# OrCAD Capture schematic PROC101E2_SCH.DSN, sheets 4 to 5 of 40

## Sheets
4 09.SOC POWER: size C; title: SOC POWER
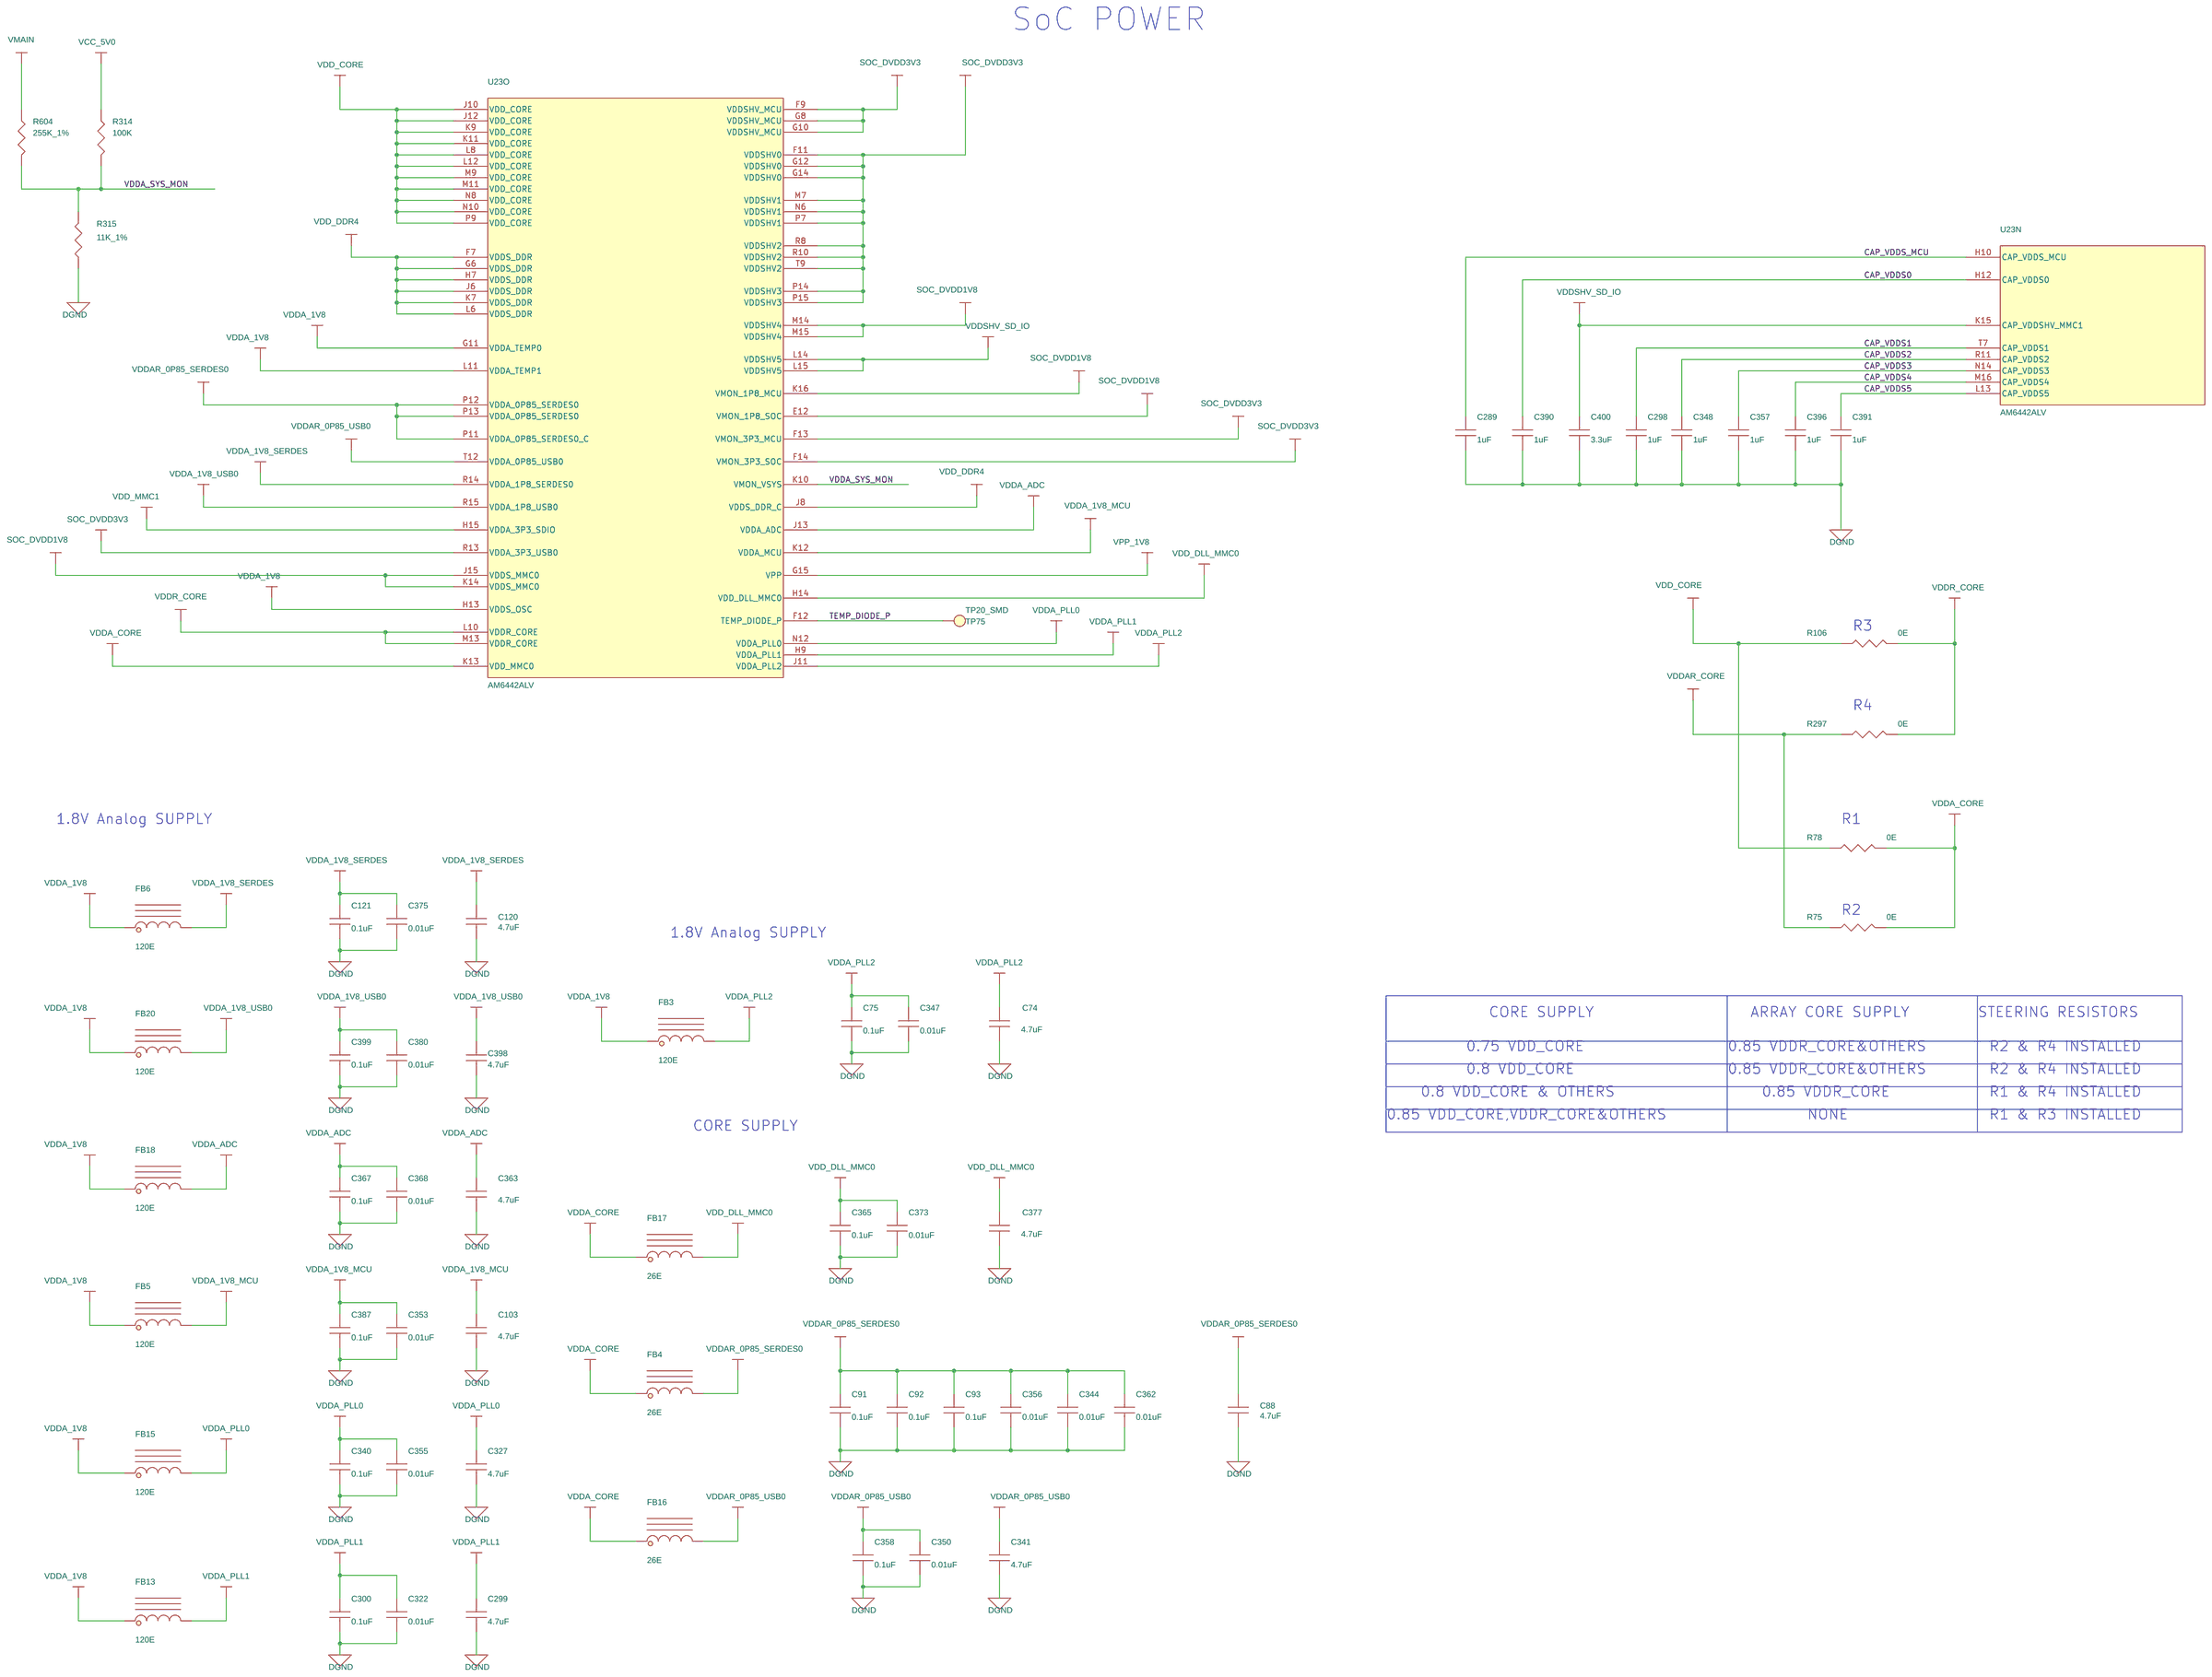
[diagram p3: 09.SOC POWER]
5 30.PCIe INTERFACE: size C; title: PCIe INTERFACE; note: PROC067
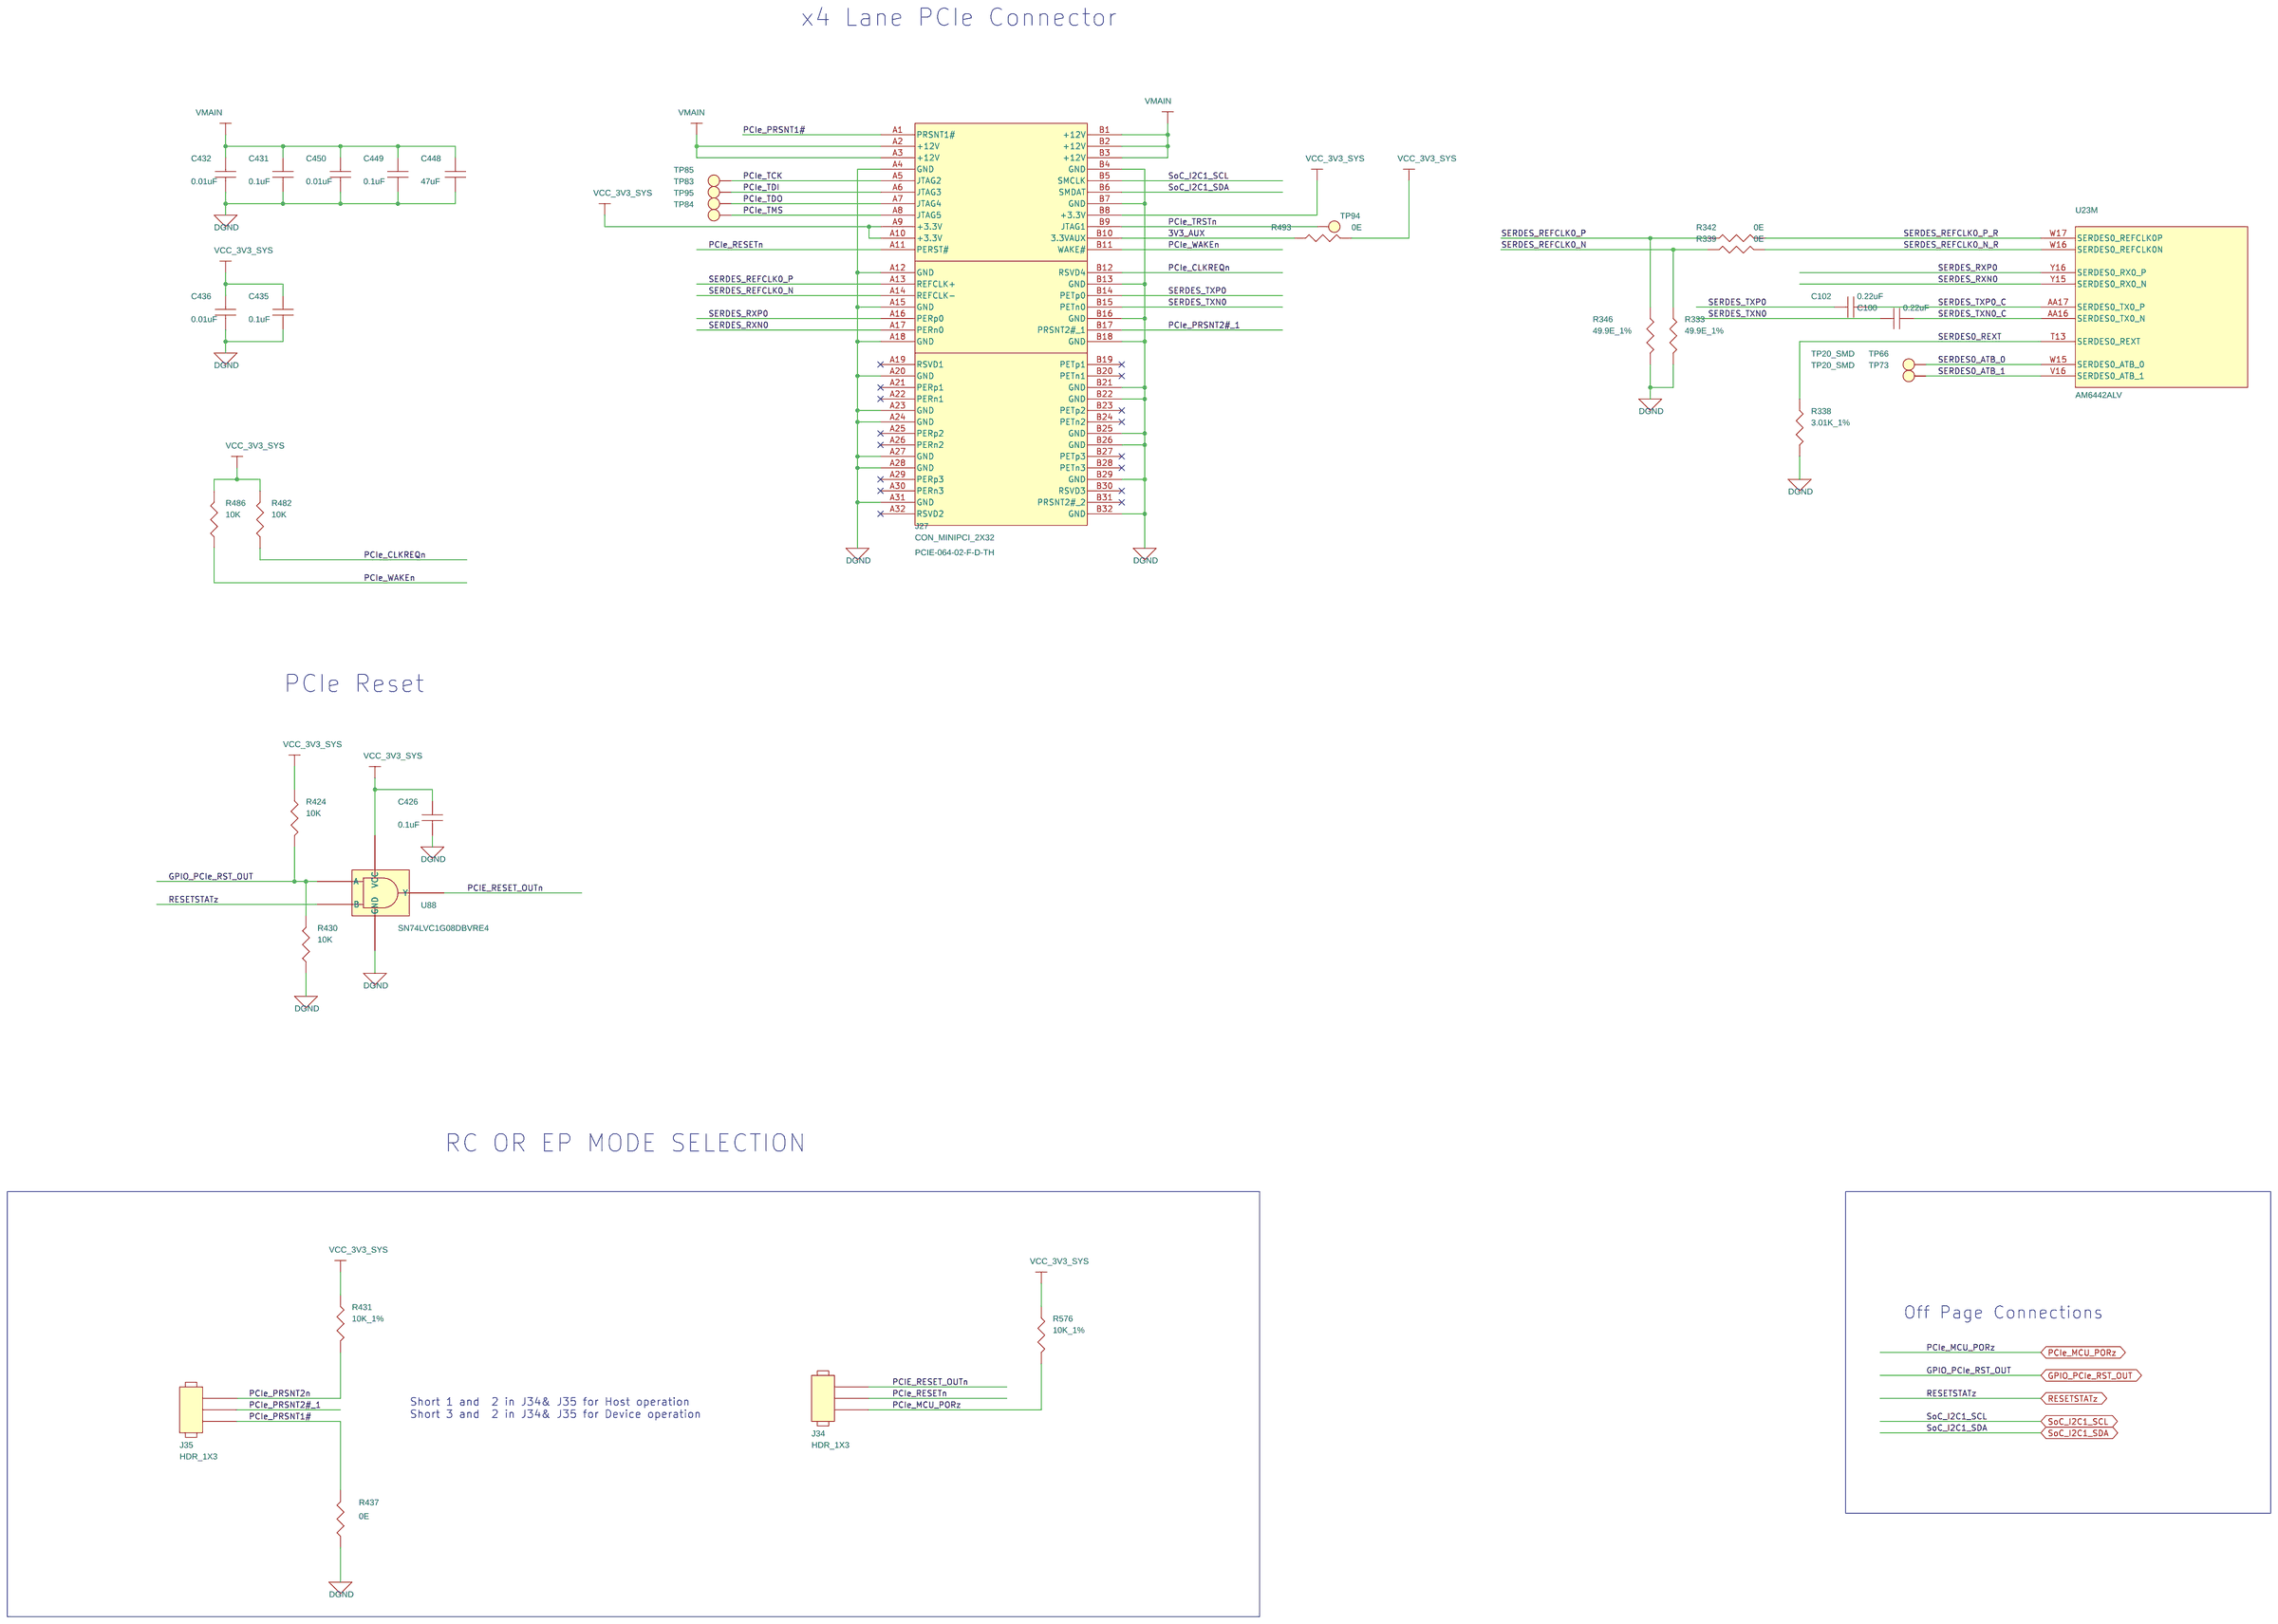
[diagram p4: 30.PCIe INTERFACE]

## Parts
sheet 09.SOC POWER
C74  4.7uF  [CAP0402_0-75]
C75  0.1uF  [CAP0201_0-5]
C88  4.7uF  [CAP0402_0-75]
C91  0.1uF  [CAP0201_0-5]
C92  0.1uF  [CAP0201_0-5]
C93  0.1uF  [CAP0201_0-5]
C103  4.7uF  [CAP0402_0-75]
C120  4.7uF  [CAP0402_0-75]
C121  0.1uF  [CAP0201_0-5]
C289  1uF  [CAP0201_0-5]
C298  1uF  [CAP0201_0-5]
C299  4.7uF  [CAP0402_0-75]
C300  0.1uF  [CAP0201_0-5]
C322  0.01uF  [CAP0201_0-5]
C327  4.7uF  [CAP0402_0-75]
C340  0.1uF  [CAP0201_0-5]
C341  4.7uF  [CAP0402_0-75]
C344  0.01uF  [CAP0201_0-5]
C347  0.01uF  [CAP0201_0-5]
C348  1uF  [CAP0201_0-5]
C350  0.01uF  [CAP0201_0-5]
C353  0.01uF  [CAP0201_0-5]
C355  0.01uF  [CAP0201_0-5]
C356  0.01uF  [CAP0201_0-5]
C357  1uF  [CAP0201_0-5]
C358  0.1uF  [CAP0201_0-5]
C362  0.01uF  [CAP0201_0-5]
C363  4.7uF  [CAP0402_0-75]
C365  0.1uF  [CAP0201_0-5]
C367  0.1uF  [CAP0201_0-5]
C368  0.01uF  [CAP0201_0-5]
C373  0.01uF  [CAP0201_0-5]
C375  0.01uF  [CAP0201_0-5]
C377  4.7uF  [CAP0402_0-75]
C380  0.01uF  [CAP0201_0-5]
C387  0.1uF  [CAP0201_0-5]
C390  1uF  [CAP0201_0-5]
C391  1uF  [CAP0201_0-5]
C396  1uF  [CAP0201_0-5]
C398  4.7uF  [CAP0402_0-75]
C399  0.1uF  [CAP0201_0-5]
C400  3.3uF  [CAP0402_0-75]
FB3  120E  [IND0603_1]
FB4  26E  [IND0603_1]
FB5  120E  [IND0603_1]
FB6  120E  [IND0603_1]
FB13  120E  [IND0603_1]
FB15  120E  [IND0603_1]
FB16  26E  [IND0603_1]
FB17  26E  [IND0603_1]
FB18  120E  [IND0603_1]
FB20  120E  [IND0603_1]
R75  0E  [RES1210_0-75]
R78  0E  [RES1210_0-75]
R106  0E  [RES1210_0-75]
R297  0E  [RES1210_0-75]
R314  100K  [RES0402_0-5]
R315  11K_1%  [RES0402_0-5]
R604  255K_1%  [RES0402_0-5]
TP75  TP20_SMD  [TP20_SMD]
sheet 11.SOC VSS
U23  AM6442ALV  [FCBGA441_31-49_680X680_2-6]  (sections A,B,C,D,E,F,G,H,I,J,K,L,M,N,O,P)
sheet 30.PCIe INTERFACE
C100  0.22uF  [CAP0201_0-5]
C102  0.22uF  [CAP0201_0-5]
C426  0.1uF  [CAP0402_0-75]
C431  0.1uF  [CAP0402_0-75]
C432  0.01uF  [CAP0402_0-75]
C435  0.1uF  [CAP0402_0-75]
C436  0.01uF  [CAP0402_0-75]
C448  47uF  [CAP1206_2]
C449  0.1uF  [CAP0402_0-75]
C450  0.01uF  [CAP0402_0-75]
J27  CON_MINIPCI_2X32  [CON_MINIPCI2X32_PCIE-064-02_S_S_T_11]
J34  HDR_1X3  [HDR_3X1_100_S_T]
J35  HDR_1X3  [HDR_3X1_100_S_T]
R333  49.9E_1%  [RES0402_0-5]
R338  3.01K_1%  [RES0402_0-5]
R339  0E  [RES0402_0-5]
R342  0E  [RES0402_0-5]
R346  49.9E_1%  [RES0402_0-5]
R424  10K  [RES0402_0-5]
R430  10K  [RES0402_0-5]
R431  10K_1%  [RES0402_0-5]
R437  0E  [RES0402_0-5]
R482  10K  [RES0402_0-5]
R486  10K  [RES0402_0-5]
R493  0E  [RES0402_0-5]
R576  10K_1%  [RES0402_0-5]
TP66  TP20_SMD  [TP20_SMD]
TP73  TP20_SMD  [TP20_SMD]
TP83  TP20_SMD  [TP20_SMD]
TP84  TP20_SMD  [TP20_SMD]
TP85  TP20_SMD  [TP20_SMD]
TP94  TP20_SMD  [TP20_SMD]
TP95  TP20_SMD  [TP20_SMD]
U88  SN74LVC1G08DBVRE4  [SOT23-5]

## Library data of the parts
C74 C88 C103 C120 C299 C327 C341 C363 C377 C398 = CAP: CAP CERAMIC 4.7uF 10V 20% X5R 0402; Chkd/date: MANIRAJA/230118; Crtd /date: MANIRAJA/230118; Custom_Duty: 15%; Customs_HS_Code: 85322990; Distributor_name: DIGIKEY; Distributor_part_number: 478-10791-1-ND; Footprint Path: Y:\MIS_DATABASE\Library\ALTIUM_TOOL\PCB_FOOTPRINTS\Altium_Footprint_Lib.PcbLib; Height: 0.71MM; Library Path: Y:\MIS_DATABASE\Library\ALTIUM_TOOL\SCHEMATICS_PARTS\MS_DISCRETE_Library.schlib; Mfr_name: AVX CORPORATION; Mfr_part_number: 0402ZD475MAT2A; Mistral Part No: 120012060002-R; Package: 0402; Part_type: CAPACITORS\CERAMIC; Project: TI_MAXIE_CPB; RoHS: RoHS; Temperature: -55°C+85°C; Tolerance: 20%; Voltage: 10V; Wattage: NA; Weight: 0.65mg; Datasheet: Y:\MIS_DATABASE\DATASHEETS\CAPACITORS\AVX_MLC.PDF
C75 C91-C93 C121 C300 C340 C358 C365 C367 C387 C399 = CAP: CAP CERAMIC 0.1uF 16V 10% X5R 0201; Chkd/date: MANIRAJA/120218; Crtd /date: MANIRAJA/120218; Custom_Duty: 15%; Customs_HS_Code: 85322990; Distributor_name: DIGIKEY; Distributor_part_number: 490-16742-1-ND; Footprint Path: Y:\MIS_DATABASE\Library\ALTIUM_TOOL\PCB_FOOTPRINTS\Altium_Footprint_Lib.PcbLib; Height: 0.33MM; Library Path: Y:\MIS_DATABASE\Library\ALTIUM_TOOL\SCHEMATICS_PARTS\MS_DISCRETE_Library.schlib; Mfr_name: MURATA; Mfr_part_number: GRM033R61C104KE84J; Mistral Part No: 120009030072-R; Package: 0201; Part_type: CAPACITORS\CERAMIC; Project: TI_MAXIE_CPB; RoHS: RoHS; Temperature: -55°C+85°C; Tolerance: 10%; Voltage: 16V; Wattage: NA; Weight: 0.33mg; Datasheet: Y:\MIS_DATABASE\DATASHEETS\CAPACITORS\GRM033R61C104KE84.PDF
C289 C298 C348 C357 C390 C391 C396 = CAP: CAP CERAMIC 1uF 6.3V 20% X5R 0201; Chkd/date: MANIRAJA/091219; Crtd /date: ALVY/091219; Custom_Duty: 15%; Customs_HS_Code: 85322990; Distributor_name: DIGIKEY; Distributor_part_number: 490-7229-1-ND; Footprint Path: Y:\MIS_DATABASE\Library\ALTIUM_TOOL\PCB_FOOTPRINTS\Altium_Footprint_Lib.PcbLib; Height: 0.35MM; Library Path: Y:\MIS_DATABASE\Library\ALTIUM_TOOL\SCHEMATICS_PARTS\MS_DISCRETE_Library.schlib; Mfr_name: MURATA; Mfr_part_number: GRM033R60J105MEA2D; Mistral Part No: 120012060001-R; Package: 0201; Part_type: CAPACITORS\CERAMIC; Project: MYTHIC_X16_BRD; RoHS: RoHS; Temperature: -55°C+85°C; Tolerance: 20%; Voltage: 6.3V; Wattage: NA; Weight: 7mg; Datasheet: Y:\MIS_DATABASE\DATASHEETS\CAPACITORS\GRM033R60J105MEA2.PDF
C322 C344 C347 C350 C353 C355 C356 C362 C368 C373 C375 C380 = CAP: CAP CERAMIC 0.01uF 25V 10% X5R 0201; Chkd/date: MANIRAJA/230118; Crtd /date: MANIRAJA/230118; Custom_Duty: 15%; Customs_HS_Code: 85322990; Distributor_name: DIGIKEY; Distributor_part_number: GRM033R61E103KA12J-ND; Footprint Path: Y:\MIS_DATABASE\Library\ALTIUM_TOOL\PCB_FOOTPRINTS\Altium_Footprint_Lib.PcbLib; Height: 0.33MM; Library Path: Y:\MIS_DATABASE\Library\ALTIUM_TOOL\SCHEMATICS_PARTS\MS_DISCRETE_Library.schlib; Mfr_name: MURATA; Mfr_part_number: GRM033R61E103KA12J; Mistral Part No: 120018010007-R; Package: 0201; Part_type: CAPACITORS\CERAMIC; Project: TI_MAXIE_CPB; RoHS: RoHS; Temperature: -55°C+85°C; Tolerance: 10%; Voltage: 25V; Wattage: NA; Weight: 0.33mg; Datasheet: Y:\MIS_DATABASE\DATASHEETS\CAPACITORS\GRM033R61E103KA12.PDF
C400 = CAP: CAP CERAMIC 3.3uF 10V 10% X5R 0402; Chkd/date: ALVY/190320; Crtd /date: ALVY/190320; Custom_Duty: 15%; Customs_HS_Code: 85322990; Distributor_name: DIGIKEY; Distributor_part_number: 445-13819-1-ND; Footprint Path: Y:\MIS_DATABASE\Library\ALTIUM_TOOL\PCB_FOOTPRINTS\Altium_Footprint_Lib.PcbLib; Height: 0.60MM; Library Path: Y:\MIS_DATABASE\Library\ALTIUM_TOOL\SCHEMATICS_PARTS\MS_DISCRETE_Library.schlib; Mfr_name: TDK CORPORATION; Mfr_part_number: C1005X5R1A335K050BC; Mistral Part No: 120020030002-R; Package: 0402; Part_type: CAPACITORS\CERAMIC; Project: 32CHSCC_V3_PREAMP-CA; RoHS: RoHS; Temperature: -55°C+85°C; Tolerance: 10%; Voltage: 10V; Wattage: NA; Weight: 34mg; Datasheet: Y:\MIS_DATABASE\DATASHEETS\CAPACITORS\TDK-C-SER_JUL17.PDF
FB3 FB5 FB6 FB13 FB15 FB18 FB20 = INDUCTOR_FERRITE: IND FERRITE BEAD CHIP 120E 2A 0603; Chkd/date: MANIRAJA/180820; Crtd /date: ALVY/180820; Custom_Duty: 24%; Customs_HS_Code: 85437099; Distributor_name: DIGIKEY; Distributor_part_number: 732-782631141CT-ND; Footprint Path: Y:\MIS_DATABASE\Library\ALTIUM_TOOL\PCB_FOOTPRINTS\Altium_Footprint_Lib.PcbLib; Height: 1.00MM; Library Path: Y:\MIS_DATABASE\Library\ALTIUM_TOOL\SCHEMATICS_PARTS\MS_FILTER_Library.schlib; Mfr_name: WURTH ELECTRONICS; Mfr_part_number: 782631141; Mistral Part No: 130020080015-R; Package: 0603; Part_type: INDUCTOR; Project: AM64x_EVM_BRD; RoHS: RoHS; Temperature: -55°C+125°C; Tolerance: 25%; Voltage: NA; Wattage: NA; Weight: NA; Datasheet: Y:\MIS_DATABASE\DATASHEETS\DISCRETES\INDUCTORS\782631141.PDF
FB4 FB16 FB17 = INDUCTOR_FERRITE: IND FERRITE BEAD CHIP 26E 6.5A 0603; Chkd/date: MANIRAJA/180820; Crtd /date: ALVY/180820; Custom_Duty: 24%; Customs_HS_Code: 85437099; Distributor_name: DIGIKEY; Distributor_part_number: 732-6117-1-ND; Footprint Path: Y:\MIS_DATABASE\Library\ALTIUM_TOOL\PCB_FOOTPRINTS\Altium_Footprint_Lib.PcbLib; Height: 1.00MM; Library Path: Y:\MIS_DATABASE\Library\ALTIUM_TOOL\SCHEMATICS_PARTS\MS_FILTER_Library.schlib; Mfr_name: WURTH ELECTRONICS; Mfr_part_number: 74279228260; Mistral Part No: 130020080017-R; Package: 0603; Part_type: INDUCTOR; Project: AM64x_EVM_BRD; RoHS: RoHS; Temperature: -55°C+125°C; Tolerance: 25%; Voltage: NA; Wattage: NA; Weight: 2mg; Datasheet: Y:\MIS_DATABASE\DATASHEETS\DISCRETES\INDUCTORS\74279228260.PDF
R75 R297 = RESISTOR: RES 0E 1/2W 5% 1210; Chkd/date: VASANTHA/281216; Crtd /date: USMAN/080109; Custom_Duty: 15%; Customs_HS_Code: 85332119; Distributor_name: MOUSER; Distributor_part_number: 603-RC1210JR-070RL; Footprint Path: Y:\MIS_DATABASE\Library\ALTIUM_TOOL\PCB_FOOTPRINTS\Altium_Footprint_Lib.PcbLib; Height: 0.65MM; Library Path: Y:\MIS_DATABASE\Library\ALTIUM_TOOL\SCHEMATICS_PARTS\MS_DISCRETE_Library.schlib; Mfr_name: YAGEO AMERICA; Mfr_part_number: RC1210JR-070RL; Mistral Part No: 110009030080-R; Package: 1210; Part_type: RESISTORS\FIXED; Project: OMAP_EVM; RoHS: RoHS; Temperature: -55°C+155°C; Tolerance: 5%; Voltage: NA; Wattage: 1/2W; Weight: 10mg; Datasheet: Y:\MIS_DATABASE\DATASHEETS\RESISTORS\RCXXXXL-SER_MAR18.PDF
R78 R106 = RESISTOR: RES 0E 1/2W 5% 1210; Assembly: DNI; Chkd/date: VASANTHA/281216; Crtd /date: USMAN/080109; Custom_Duty: 15%; Customs_HS_Code: 85332119; Distributor_name: MOUSER; Distributor_part_number: 603-RC1210JR-070RL; Footprint Path: Y:\MIS_DATABASE\Library\ALTIUM_TOOL\PCB_FOOTPRINTS\Altium_Footprint_Lib.PcbLib; Height: 0.65MM; Library Path: Y:\MIS_DATABASE\Library\ALTIUM_TOOL\SCHEMATICS_PARTS\MS_DISCRETE_Library.schlib; Mfr_name: YAGEO AMERICA; Mfr_part_number: RC1210JR-070RL; Mistral Part No: 110009030080-R; Package: 1210; Part_type: RESISTORS\FIXED; Project: OMAP_EVM; RoHS: RoHS; Temperature: -55°C+155°C; Tolerance: 5%; Voltage: NA; Wattage: 1/2W; Weight: 10mg; Datasheet: Y:\MIS_DATABASE\DATASHEETS\RESISTORS\RCXXXXL-SER_MAR18.PDF
R314 = RESISTOR: RES 100K 1/16W 5% 0402; Chkd/date: VASANTHA/061216; Crtd /date: BAVISH/010611; Custom_Duty: 15%; Customs_HS_Code: 85332119; Distributor_name: DIGIKEY; Distributor_part_number: 541-100KJCT-ND; Footprint Path: Y:\MIS_DATABASE\Library\ALTIUM_TOOL\PCB_FOOTPRINTS\Altium_Footprint_Lib.PcbLib; Height: 0.40MM; Library Path: Y:\MIS_DATABASE\Library\ALTIUM_TOOL\SCHEMATICS_PARTS\MS_DISCRETE_Library.schlib; Mfr_name: VISHAY; Mfr_part_number: CRCW0402100KJNED; Mistral Part No: 110011060002-R; Package: 0402; Part_type: RESISTORS\FIXED; Project: AM4515_EVM_LCD; RoHS: RoHS; Temperature: -55°C+155°C; Tolerance: 5%; Voltage: NA; Wattage: 1/16W; Weight: 0.65mg; Datasheet: Y:\MIS_DATABASE\DATASHEETS\RESISTORS\CRCW0603.PDF
R315 = RESISTOR: RES 11K 1/16W 1% 0402; Chkd/date: VASANTHA/251115; Crtd /date: VASANTHA/251115; Custom_Duty: 15%; Customs_HS_Code: 85332119; Distributor_name: DIGIKEY; Distributor_part_number: 311-11.0KLRCT-ND; Footprint Path: Y:\MIS_DATABASE\Library\ALTIUM_TOOL\PCB_FOOTPRINTS\Altium_Footprint_Lib.PcbLib; Height: 0.40MM; Library Path: Y:\MIS_DATABASE\Library\ALTIUM_TOOL\SCHEMATICS_PARTS\MS_DISCRETE_Library.schlib; Mfr_name: YAGEO AMERICA; Mfr_part_number: RC0402FR-0711KL; Mistral Part No: 110015110012-R; Package: 0402; Part_type: RESISTORS\FIXED; Project: TI_VLAN_SWITCH; RoHS: RoHS; Temperature: -55°C+155°C; Tolerance: 1%; Voltage: NA; Wattage: 1/16W; Weight: 0.65mg; Datasheet: Y:\MIS_DATABASE\DATASHEETS\RESISTORS\RCXXXXL-SER_MAR18.PDF
R604 = RESISTOR: RES 255K 1/10W 1% 0402; Assembly: DNI; Chkd/date: MANIRAJA/160218; Crtd /date: MANIRAJA/160218; Custom_Duty: 15%; Customs_HS_Code: 85332119; Distributor_name: DIGIKEY; Distributor_part_number: P255KLCT-ND; Footprint Path: Y:\MIS_DATABASE\Library\ALTIUM_TOOL\PCB_FOOTPRINTS\Altium_Footprint_Lib.PcbLib; Height: 0.40MM; Library Path: Y:\MIS_DATABASE\Library\ALTIUM_TOOL\SCHEMATICS_PARTS\MS_DISCRETE_Library.schlib; Mfr_name: PANASONIC-ECG; Mfr_part_number: ERJ-2RKF2553X; Mistral Part No: 110018020016-R; Package: 0402; Part_type: RESISTORS\FIXED; Project: NPOL_SAR_ADC; RoHS: RoHS; Temperature: -55°C+155°C; Tolerance: 1%; Voltage: NA; Wattage: 1/10W; Weight: 0.8mg; Datasheet: Y:\MIS_DATABASE\DATASHEETS\RESISTORS\PAN-ERJSER_NOV17.PDF
TP66 TP73 TP75 TP83-TP85 TP94 TP95 = TESTPOINT: TESTPOINT CIR 20 SMD; Chkd/date: SHREESHAIL/171006; Crtd /date: MAZHAR/171006; Custom_Duty: NA; Customs_HS_Code: NA; Distributor_name: NA; Distributor_part_number: NA; Footprint Path: Y:\MIS_DATABASE\Library\ALTIUM_TOOL\PCB_FOOTPRINTS\Altium_Footprint_Lib.PcbLib; Height: NA; Library Path: Y:\MIS_DATABASE\Library\ALTIUM_TOOL\SCHEMATICS_PARTS\MS_DISCRETE_Library.schlib; MECHANICAL 3D STEP FILE: NA; Mfr_name: LOCAL; Mistral Part No: NA; Package: SMD; Project: BT MODULE_CSRBC04; RoHS: NA; Temperature: NA; Tolerance: NA; Voltage: NA; Wattage: NA; Weight: NA; Datasheet: NA
U23 = AM64-SVB_BGA441: IC AM64 SoC MICROPROCESSOR BGA441; Chkd/date: MANIRAJA/020520; Crtd /date: ALVY/090420; Custom_Duty: 15%; Customs_HS_Code: 85423100; Distributor_name: NA; Distributor_part_number: NA; Footprint Path: Y:\MIS_DATABASE\Library\ALTIUM_TOOL\PCB_FOOTPRINTS\Altium_Footprint_Lib.PcbLib; Height: 2.57MM; Library Path: Y:\MIS_DATABASE\Library\ALTIUM_TOOL\SCHEMATICS_PARTS\MS_MICROPROCESSOR_Library.schlib; Mfr_name: TEXAS INSTRUMENTS; Mfr_part_number: AM6442ASFGGAALV; Mistral Part No: 141220040002; Package: BGA441; Part_type: ICS\DIGITAL\MICROPROCESSOR; Project: AM64x_SVB BRD; RoHS: NA; Temperature: NA; Tolerance: NA; Voltage: NA; Wattage: NA; Weight: NA; Datasheet: Y:\MIS_DATABASE\DATASHEETS\ICS\DIGITAL\MICROCONTROLLER\AM64-SoC_SVB.PDF
C100 C102 = CAP: CAP CERAMIC 0.22uF 6.3V 10% X6S AUTO 0201; Chkd/date: MANIRAJA/220219; Crtd /date: ALVY/220219; Custom_Duty: 15%; Customs_HS_Code: 85322990; Distributor_name: DIGIKEY; Distributor_part_number: 490-12230-1-ND; Footprint Path: Y:\MIS_DATABASE\Library\ALTIUM_TOOL\PCB_FOOTPRINTS\Altium_Footprint_Lib.PcbLib; Height: 0.33MM; Library Path: Y:\MIS_DATABASE\Library\ALTIUM_TOOL\SCHEMATICS_PARTS\MS_DISCRETE_Library.schlib; Mfr_name: MURATA; Mfr_part_number: GRT033C80J224KE01D; Mistral Part No: 120019020011-R; Package: 0201; Part_type: CAPACITORS\CERAMIC; Project: TI_J7ES_EVM_SOM; RoHS: RoHS; Temperature: -55°C+105°C; Tolerance: 10%; Voltage: 6.3V; Wattage: NA; Weight: 0.17mg; Datasheet: Y:\MIS_DATABASE\DATASHEETS\CAPACITORS\MURATA-GCM-SER.PDF
C426 C431 C435 C449 = CAP: CAP CERAMIC 0.1uF 25V 20% X5R 0402; Alt_Mfr_name: YAGEO AMERICA; Alt_Mfr_part_number: CC0402KRX5R8BB104; Chkd/date: MANIRAJA/170820; Crtd /date: ALVY/170820; Custom_Duty: 15%; Customs_HS_Code: 85322990; Distributor_name: DIGIKEY; Distributor_part_number: 732-7495-1-ND; Footprint Path: Y:\MIS_DATABASE\Library\ALTIUM_TOOL\PCB_FOOTPRINTS\Altium_Footprint_Lib.PcbLib; Height: 0.55MM; Library Path: Y:\MIS_DATABASE\Library\ALTIUM_TOOL\SCHEMATICS_PARTS\MS_DISCRETE_Library.schlib; Mfr_name: WURTH ELECTRONICS; Mfr_part_number: 885012105018; Mistral Part No: 120020080003-R; Package: 0402; Part_type: CAPACITORS\CERAMIC; Project: AM64x_EVM_BRD; RoHS: RoHS; Temperature: -55°C+85°C; Tolerance: 20%; Voltage: 25V; Wattage: NA; Weight: 0.65mg; Datasheet: Y:\MIS_DATABASE\DATASHEETS\CAPACITORS\885012105018.PDF
C432 C436 C450 = CAP: CAP CERAMIC 0.01uF 25V 10% X7R 0402; Chkd/date: MANIRAJA/170820; Crtd /date: ALVY/170820; Custom_Duty: 15%; Customs_HS_Code: 85322990; Distributor_name: DIGIKEY; Distributor_part_number: 732-7545-1-ND; Footprint Path: Y:\MIS_DATABASE\Library\ALTIUM_TOOL\PCB_FOOTPRINTS\Altium_Footprint_Lib.PcbLib; Height: 0.55MM; Library Path: Y:\MIS_DATABASE\Library\ALTIUM_TOOL\SCHEMATICS_PARTS\MS_DISCRETE_Library.schlib; Mfr_name: WURTH ELECTRONICS; Mfr_part_number: 885012205050; Mistral Part No: 120011090040-R; Package: 0402; Part_type: CAPACITORS\CERAMIC; Project: AM64x_EVM_BRD; RoHS: RoHS; Temperature: -55°C+125°C; Tolerance: 10%; Voltage: 25V; Wattage: NA; Weight: 0.65mg; Datasheet: Y:\MIS_DATABASE\DATASHEETS\CAPACITORS\885012205050.PDF
C448 = CAP: CAP CERAMIC 47uF 25V 20% X5R 1206; Chkd/date: MANIRAJA/230118; Crtd /date: MANIRAJA/230118; Custom_Duty: 15%; Customs_HS_Code: 85322990; Distributor_name: DIGIKEY; Distributor_part_number: 490-16268-1-ND; Footprint Path: Y:\MIS_DATABASE\Library\ALTIUM_TOOL\PCB_FOOTPRINTS\Altium_Footprint_Lib.PcbLib; Height: 1.80MM; Library Path: Y:\MIS_DATABASE\Library\ALTIUM_TOOL\SCHEMATICS_PARTS\MS_DISCRETE_Library.schlib; Mfr_name: MURATA; Mfr_part_number: GRM31CR61E476ME44L; Mistral Part No: 120013050002-R; Package: 1206; Part_type: CAPACITORS\CERAMIC; Project: TI_MAXIE_CPB; RoHS: RoHS; Temperature: -55°C+85°C; Tolerance: 20%; Voltage: 25V; Wattage: NA; Weight: 40mg; Datasheet: Y:\MIS_DATABASE\DATASHEETS\CAPACITORS\MURATA-GXX-SER_NOV17.PDF
J27 = CON_MINIPCI_32X2: CON MINIPCI 2X32 1.00MM PITCH SOCKET ST TH; Chkd/date: MANIRAJA/101017; Crtd /date: MANIRAJA/101017; Custom_Duty: 24%; Customs_HS_Code: 85369090; Distributor_name: DIGIKEY; Distributor_part_number: SAM9742-ND; Height: 11.00MM; Mfr_name: SAMTEC; Mfr_part_number: PCIE-064-02-F-D-TH; Mistral Part No: 150017100015-R; Package: THRU-HOLE; Part_type: CONNECTOR\PCI; Project: TI_SVB_MAXWELL_SPM; RoHS: RoHS; TEXT: PCIe x2; Temperature: -55°C+125°C; Tolerance: NA; Voltage: NA; Wattage: NA; Weight: NA; Datasheet: Y:\MIS_DATABASE\DATASHEETS\CONNECTORS\SAMTEC-PCIE-TH.PDF
J34 J35 = HEADER_3X1: HDR 1X3 2.54MM PITCH ST TH; Chkd/date: VASANTHA/290616; Crtd /date: VASANTHA/290616; Custom_Duty: 15%; Customs_HS_Code: 85322990; Distributor_name: DIGIKEY; Distributor_part_number: 609-3471-ND; Height: 8.58MM; Mfr_name: FCI; Mfr_part_number: 68001-403HLF; Mistral Part No: 150016060025-R; Package: THRU-HOLE; Part_type: CONNECTOR\HEADERS; Project: IKEYP; RoHS: RoHS; TEXT: REST; TEXT1: INT; TEXT2: EXT; Temperature: -40°C+105°C; Tolerance: NA; Voltage: NA; Wattage: NA; Weight: NA; Datasheet: Y:\MIS_DATABASE\DATASHEETS\CONNECTORS\68000.PDF
R333 R346 = RESISTOR: RES 49.9E 1/16W 1% 0402; Chkd/date: MANIRAJA/210519; Crtd /date: MANIRAJA/210519; Custom_Duty: 15%; Customs_HS_Code: 85332119; Distributor_name: DIGIKEY; Distributor_part_number: 541-3967-1-ND; Footprint Path: Y:\MIS_DATABASE\Library\ALTIUM_TOOL\PCB_FOOTPRINTS\Altium_Footprint_Lib.PcbLib; Height: 0.35MM; Library Path: Y:\MIS_DATABASE\Library\ALTIUM_TOOL\SCHEMATICS_PARTS\MS_DISCRETE_Library.schlib; Mfr_name: VISHAY; Mfr_part_number: CRCW040249R9FKEDC; Mistral Part No: 110009030846-R; Package: 0402; Part_type: RESISTORS\FIXED; Project: RFSU_RFTJ_CARD; RoHS: RoHS; Temperature: -55°C+155°C; Tolerance: 1%; Voltage: NA; Wattage: 1/16W; Weight: 0.65mg; Datasheet: Y:\MIS_DATABASE\DATASHEETS\RESISTORS\CRCW_C-SER.PDF
R338 = RESISTOR: RES 3.01K 1/16W 1% 0402; Chkd/date: MANIRAJA/150620; Crtd /date: ALVY/120620; Custom_Duty: 15%; Customs_HS_Code: 85332119; Distributor_name: DIGIKEY; Distributor_part_number: 541-3.01KLCT-ND; Footprint Path: Y:\MIS_DATABASE\Library\ALTIUM_TOOL\PCB_FOOTPRINTS\Altium_Footprint_Lib.PcbLib; Height: 0.40MM; Library Path: Y:\MIS_DATABASE\Library\ALTIUM_TOOL\SCHEMATICS_PARTS\MS_DISCRETE_Library.schlib; Mfr_name: VISHAY; Mfr_part_number: CRCW04023K01FKED; Mistral Part No: 110020060037-R; Package: 0402; Part_type: RESISTORS\FIXED; Project: AM64x-GP_EVM BRD; RoHS: RoHS; Temperature: -55°C+155°C; Tolerance: 1%; Voltage: NA; Wattage: 1/16W; Weight: 0.65mg; Datasheet: Y:\MIS_DATABASE\DATASHEETS\RESISTORS\CRCW0603.PDF
R339 R342 = RESISTOR: RES 0E 1/16W JUMPER 0402; Chkd/date: VASANTHA/201216; Crtd /date: MUDDU/190810; Custom_Duty: 15%; Customs_HS_Code: 85332119; Distributor_name: DIGIKEY; Distributor_part_number: 541-0.0JCT-ND; Footprint Path: Y:\MIS_DATABASE\Library\ALTIUM_TOOL\PCB_FOOTPRINTS\Altium_Footprint_Lib.PcbLib; Height: 0.40MM; Library Path: Y:\MIS_DATABASE\Library\ALTIUM_TOOL\SCHEMATICS_PARTS\MS_DISCRETE_Library.schlib; Mfr_name: VISHAY; Mfr_part_number: CRCW04020000Z0ED; Mistral Part No: 110010080019-R; Package: 0402; Part_type: RESISTORS\FIXED; Project: PB_BUGBASE; RoHS: RoHS; SIGNAL_MODEL: RESISTOR_RES0402_22E_1%_22E_1%; Temperature: -55°C+155°C; Tolerance: NA; Voltage: NA; Wattage: 1/16W; Weight: 0.65mg; Datasheet: Y:\MIS_DATABASE\DATASHEETS\RESISTORS\CRCW0603.PDF
R424 = RESISTOR: RES 10K 1/16W 5% 0402; Assembly: DNI; Chkd/date: VASANTHA/061216; Crtd /date: MAZHAR/230805; Custom_Duty: 15%; Customs_HS_Code: 85332119; Distributor_name: DIGIKEY; Distributor_part_number: 311-10KJRCT-ND; Footprint Path: Y:\MIS_DATABASE\Library\ALTIUM_TOOL\PCB_FOOTPRINTS\Altium_Footprint_Lib.PcbLib; Height: 0.40MM; Library Path: Y:\MIS_DATABASE\Library\ALTIUM_TOOL\SCHEMATICS_PARTS\MS_DISCRETE_Library.schlib; Mfr_name: YAGEO AMERICA; Mfr_part_number: RC0402JR-0710KL; Mistral Part No: 110011060021-R; Package: 0402; Part_type: RESISTORS\FIXED; Project: HSE; RoHS: RoHS; Temperature: -55°C+155°C; Tolerance: 5%; Voltage: NA; Wattage: 1/16W; Weight: 0.65mg; Datasheet: Y:\MIS_DATABASE\DATASHEETS\RESISTORS\RCXXXXL-SER_MAR18.PDF
R430 R482 R486 = RESISTOR: RES 10K 1/16W 5% 0402; Chkd/date: VASANTHA/061216; Crtd /date: MAZHAR/230805; Custom_Duty: 15%; Customs_HS_Code: 85332119; Distributor_name: DIGIKEY; Distributor_part_number: 311-10KJRCT-ND; Footprint Path: Y:\MIS_DATABASE\Library\ALTIUM_TOOL\PCB_FOOTPRINTS\Altium_Footprint_Lib.PcbLib; Height: 0.40MM; Library Path: Y:\MIS_DATABASE\Library\ALTIUM_TOOL\SCHEMATICS_PARTS\MS_DISCRETE_Library.schlib; Mfr_name: YAGEO AMERICA; Mfr_part_number: RC0402JR-0710KL; Mistral Part No: 110011060021-R; Package: 0402; Part_type: RESISTORS\FIXED; Project: HSE; RoHS: RoHS; Temperature: -55°C+155°C; Tolerance: 5%; Voltage: NA; Wattage: 1/16W; Weight: 0.65mg; Datasheet: Y:\MIS_DATABASE\DATASHEETS\RESISTORS\RCXXXXL-SER_MAR18.PDF
R431 R576 = RESISTOR: RES 10K 1/16W 1% 0402; Chkd/date: VASANTHA/201216; Crtd /date: GEETHA/290506; Custom_Duty: 15%; Customs_HS_Code: 85332119; Distributor_name: DIGIKEY; Distributor_part_number: 311-10.0KLRTR-ND; Footprint Path: Y:\MIS_DATABASE\Library\ALTIUM_TOOL\PCB_FOOTPRINTS\Altium_Footprint_Lib.PcbLib; Height: 0.40MM; Library Path: Y:\MIS_DATABASE\Library\ALTIUM_TOOL\SCHEMATICS_PARTS\MS_DISCRETE_Library.schlib; Mfr_name: YAGEO AMERICA; Mfr_part_number: RC0402FR-0710KL; Mistral Part No: 110015090015-R; Package: 0402; Part_type: RESISTORS\FIXED; Project: VOCERA; RoHS: RoHS; Temperature: -55°C+155°C; Tolerance: 1%; Voltage: NA; Wattage: 1/16W; Weight: 0.65mg; Datasheet: Y:\MIS_DATABASE\DATASHEETS\RESISTORS\RCXXXXL-SER_MAR18.PDF
R437 R493 = RESISTOR: RES 0E 1/16W JUMPER 0402; Chkd/date: VASANTHA/201216; Crtd /date: MUDDU/190810; Custom_Duty: 15%; Customs_HS_Code: 85332119; Distributor_name: DIGIKEY; Distributor_part_number: 541-0.0JCT-ND; Footprint Path: Y:\MIS_DATABASE\Library\ALTIUM_TOOL\PCB_FOOTPRINTS\Altium_Footprint_Lib.PcbLib; Height: 0.40MM; Library Path: Y:\MIS_DATABASE\Library\ALTIUM_TOOL\SCHEMATICS_PARTS\MS_DISCRETE_Library.schlib; Mfr_name: VISHAY; Mfr_part_number: CRCW04020000Z0ED; Mistral Part No: 110010080019-R; Package: 0402; Part_type: RESISTORS\FIXED; Project: PB_BUGBASE; RoHS: RoHS; Temperature: -55°C+155°C; Tolerance: NA; Voltage: NA; Wattage: 1/16W; Weight: 0.65mg; Datasheet: Y:\MIS_DATABASE\DATASHEETS\RESISTORS\CRCW0603.PDF
U88 = SN74LVC1G08DBVRE4_SOT23-5: IC SINGLE 2-INPUT POSITIVE AND GATE SOT23-5; Chkd/date: SUHAS/221010; Crtd /date: USMAN/151008; Custom_Duty: 15%; Customs_HS_Code: 85423100; Distributor_name: DIGIKEY; Distributor_part_number: SN74LVC1G08DBVRE4-ND; Height: 1.45MM; Mfr_name: TEXAS INSTRUMENTS; Mistral Part No: 141009060026-R; Part_type: ICS\DIGITAL\GATES; Project: KHAN_MAIN; RoHS: Sb/ Br FREE; Temperature: -40°C+85°C; Datasheet: Y:\MIS_DATABASE\DATASHEETS\ICS\DIGITAL\GATES\SN74LVC1G08.PDF

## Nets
3V3_AUX: J27.B10(3.3VAUX) R493.2
DGND: C74.2 C75.2 C88.2 C91.2 C92.2 C93.2 C103.2 C120.2 C121.2 C289.2 C298.2 C299.2 C300.2 C322.2 C327.2 C340.2 C341.2 C344.2 C347.2 C348.2 C350.2 C353.2 C355.2 C356.2 C357.2 C358.2 C362.2 C363.2 C365.2 C367.2 C368.2 C373.2 C375.2 C377.2 C380.2 C387.2 C390.2 C391.2 C396.2 C398.2 C399.2 C400.2 C426.2 C431.2 C432.2 C435.2 C436.2 C448.2 C449.2 C450.2 J27.A4(GND) J27.A12(GND) J27.A15(GND) J27.A18(GND) J27.A20(GND) J27.A23(GND) J27.A24(GND) J27.A27(GND) J27.A28(GND) J27.A31(GND) J27.B4(GND) J27.B7(GND) J27.B13(GND) J27.B16(GND) J27.B18(GND) J27.B21(GND) J27.B22(GND) J27.B25(GND) J27.B26(GND) J27.B29(GND) J27.B32(GND) R315.2 R333.2 R338.2 R346.2 R430.2 R437.1 U88.3(GND) ; also on sheet 2 3 6 7 8 9 10 11 12 13 14 15 16 17 18 19 20 21 22 23 24 25 26 27 28 29 30 39 40
VCC_3V3_SYS: C426.1 C435.1 C436.1 J27.A9(+3.3V) J27.A10(+3.3V) J27.B8(+3.3V) R424.1 R431.1 R482.2 R486.2 R493.1 R576.1 U88.5(VCC) ; also on sheet 2 6 7 8 10 11 12 13 14 15 16 17 18 19 20 21 23 24 25 26 27 29 30 39 40
VCC_5V0: R314.1 ; also on sheet 6 17 18 20 25
VDD_CORE: R78.1 R106.1 U23.J10(VDD_CORE) U23.J12(VDD_CORE) U23.K9(VDD_CORE) U23.K11(VDD_CORE) U23.L8(VDD_CORE) U23.L12(VDD_CORE) U23.M9(VDD_CORE) U23.M11(VDD_CORE) U23.N8(VDD_CORE) U23.N10(VDD_CORE) U23.P9(VDD_CORE) ; also on sheet 3 14 15 25
VDD_DDR4: U23.F7(VDDS_DDR) U23.G6(VDDS_DDR) U23.H7(VDDS_DDR) U23.J6(VDDS_DDR) U23.J8(VDDS_DDR_C) U23.K7(VDDS_DDR) U23.L6(VDDS_DDR) ; also on sheet 3 14 16 22
VDD_DLL_MMC0: C365.1 C373.1 C377.1 FB17.2 U23.H14(VDD_DLL_MMC0)
VDD_MMC1: U23.H15(VDDA_3P3_SDIO) ; also on sheet 3 24
VDDA_1V8: FB3.1 FB5.1 FB6.1 FB13.1 FB15.1 FB18.1 FB20.1 U23.G11(VDDA_TEMP0) U23.H13(VDDS_OSC) U23.L11(VDDA_TEMP1) ; also on sheet 3 14
VDDA_1V8_MCU: C103.1 C353.1 C387.1 FB5.2 U23.K12(VDDA_MCU)
VDDA_1V8_SERDES: C120.1 C121.1 C375.1 FB6.2 U23.R14(VDDA_1P8_SERDES0)
VDDA_1V8_USB0: C380.1 C398.1 C399.1 FB20.2 U23.R15(VDDA_1P8_USB0)
VDDA_ADC: C363.1 C367.1 C368.1 FB18.2 U23.J13(VDDA_ADC) ; also on sheet 7
VDDA_CORE: FB4.1 FB16.1 FB17.1 R75.2 R78.2 U23.K13(VDD_MMC0)
VDDA_PLL0: C327.1 C340.1 C355.1 FB15.2 U23.N12(VDDA_PLL0)
VDDA_PLL1: C299.1 C300.1 C322.1 FB13.2 U23.H9(VDDA_PLL1)
VDDA_PLL2: C74.1 C75.1 C347.1 FB3.2 U23.J11(VDDA_PLL2)
VDDA_SYS_MON: R314.2 R315.1 R604.2 U23.K10(VMON_VSYS)
VDDAR_0P85_SERDES0: C88.1 C91.1 C92.1 C93.1 C344.1 C356.1 C362.1 FB4.2 U23.P11(VDDA_0P85_SERDES0_C) U23.P12(VDDA_0P85_SERDES0) U23.P13(VDDA_0P85_SERDES0)
VDDAR_0P85_USB0: C341.1 C350.1 C358.1 FB16.2 U23.T12(VDDA_0P85_USB0)
VDDAR_CORE: R75.1 R297.1 ; also on sheet 14 15
VDDR_CORE: R106.2 R297.2 U23.L10(VDDR_CORE) U23.M13(VDDR_CORE) ; also on sheet 3 25
VDDSHV_SD_IO: C400.1 U23.K15(CAP_VDDSHV_MMC1) U23.L14(VDDSHV5) U23.L15(VDDSHV5) ; also on sheet 3 24
CAP_VDDS0: C390.1 U23.H12(CAP_VDDS0)
CAP_VDDS1: C298.1 U23.T7(CAP_VDDS1)
CAP_VDDS2: C348.1 U23.R11(CAP_VDDS2)
CAP_VDDS3: C357.1 U23.N14(CAP_VDDS3)
CAP_VDDS4: C396.1 U23.M16(CAP_VDDS4)
CAP_VDDS5: C391.1 U23.L13(CAP_VDDS5)
CAP_VDDS_MCU: C289.1 U23.H10(CAP_VDDS_MCU)
GPIO_PCIe_RST_OUT: R424.2 R430.1 U88.1(A) ; also on sheet 13
PCIe_CLKREQn: J27.B12(RSVD4) R482.1
PCIe_MCU_PORz: J34.3 R576.2 ; also on sheet 12
PCIe_PRSNT1#: J27.A1(PRSNT1#) J35.3 R437.2
PCIe_PRSNT2#_1: J27.B17(PRSNT2#_1) J35.2
PCIe_PRSNT2n: J35.1 R431.2
PCIE_RESET_OUTn: J34.1 U88.4(Y)
PCIe_RESETn: J27.A11(PERST#) J34.2
PCIe_TCK: J27.A5(JTAG2) TP85.1(TP)
PCIe_TDI: J27.A6(JTAG3) TP83.1(TP)
PCIe_TDO: J27.A7(JTAG4) TP95.1(TP)
PCIe_TMS: J27.A8(JTAG5) TP84.1(TP)
PCIe_TRSTn: J27.B9(JTAG1) TP94.1(TP)
PCIe_WAKEn: J27.B11(WAKE#) R486.1
RESETSTATz: U88.2(B) ; also on sheet 12 13 21 24 29
SERDES0_ATB_0: TP66.1(TP) U23.W15(SERDES0_ATB_0)
SERDES0_ATB_1: TP73.1(TP) U23.V16(SERDES0_ATB_1)
SERDES0_REXT: R338.1 U23.T13(SERDES0_REXT)
SERDES_REFCLK0_N: J27.A14(REFCLK-) R333.1 R339.1
SERDES_REFCLK0_N_R: R339.2 U23.W16(SERDES0_REFCLK0N)
SERDES_REFCLK0_P: J27.A13(REFCLK+) R342.1 R346.1
SERDES_REFCLK0_P_R: R342.2 U23.W17(SERDES0_REFCLK0P)
SERDES_RXN0: J27.A17(PERn0) U23.Y15(SERDES0_RX0_N)
SERDES_RXP0: J27.A16(PERp0) U23.Y16(SERDES0_RX0_P)
SERDES_TXN0: C100.1 J27.B15(PETn0)
SERDES_TXN0_C: C100.2 U23.AA16(SERDES0_TX0_N)
SERDES_TXP0: C102.1 J27.B14(PETp0)
SERDES_TXP0_C: C102.2 U23.AA17(SERDES0_TX0_P)
SOC_DVDD1V8: U23.E12(VMON_1P8_SOC) U23.J15(VDDS_MMC0) U23.K14(VDDS_MMC0) U23.K16(VMON_1P8_MCU) U23.M14(VDDSHV4) U23.M15(VDDSHV4) ; also on sheet 3 14
SoC_DVDD3V3: U23.F9(VDDSHV_MCU) U23.F11(VDDSHV0) U23.F13(VMON_3P3_MCU) U23.F14(VMON_3P3_SOC) U23.G8(VDDSHV_MCU) U23.G10(VDDSHV_MCU) U23.G12(VDDSHV0) U23.G14(VDDSHV0) U23.M7(VDDSHV1) U23.N6(VDDSHV1) U23.P7(VDDSHV1) U23.P14(VDDSHV3) U23.P15(VDDSHV3) U23.R8(VDDSHV2) U23.R10(VDDSHV2) U23.R13(VDDA_3P3_USB0) U23.T9(VDDSHV2) ; also on sheet 3 14
SoC_I2C1_SCL: J27.B5(SMCLK) ; also on sheet 6 7 10 13 14 30
SoC_I2C1_SDA: J27.B6(SMDAT) ; also on sheet 6 7 10 13 14 30
TEMP_DIODE_P: TP75.1(TP) U23.F12(TEMP_DIODE_P)
VMAIN: C431.1 C432.1 C448.1 C449.1 C450.1 J27.A2(+12V) J27.A3(+12V) J27.B1(+12V) J27.B2(+12V) J27.B3(+12V) R604.1 ; also on sheet 8 16 17
VPP_1V8: U23.G15(VPP) ; also on sheet 15

Not connected (* = marked no-connect by the designer): J27 A19(RSVD1)* A21(PERp1)* A22(PERn1)* A25(PERp2)* A26(PERn2)* A29(PERp3)* A30(PERn3)* A32(RSVD2)* B19(PETp1)* B20(PETn1)* B23(PETp2)* B24(PETn2)* B27(PETp3)* B28(PETn3)* B30(RSVD3)* B31(PRSNT2#_2)*

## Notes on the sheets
sheet 4
- SoC POWER
- R3
- R4
- 1.8V Analog SUPPLY
- R1
- R2
- 1.8V Analog SUPPLY
- CORE SUPPLY
- ARRAY CORE SUPPLY
- STEERING RESISTORS
- 0.75 VDD_CORE
- 0.85 VDDR_CORE&OTHERS
- R2 & R4 INSTALLED
- 0.8 VDD_CORE
- 0.85 VDDR_CORE&OTHERS
- R2 & R4 INSTALLED
- 0.8 VDD_CORE & OTHERS
- 0.85 VDDR_CORE
- R1 & R4 INSTALLED
- 0.85 VDD_CORE,VDDR_CORE&OTHERS
- NONE
- R1 & R3 INSTALLED
- CORE SUPPLY
sheet 5
- x4 Lane PCIe Connector
- PCIe Reset
- RC OR EP MODE SELECTION
- Off Page Connections
- Short 1 and  2 in J34& J35 for Host operation
  Short 3 and  2 in J34& J35 for Device operation
